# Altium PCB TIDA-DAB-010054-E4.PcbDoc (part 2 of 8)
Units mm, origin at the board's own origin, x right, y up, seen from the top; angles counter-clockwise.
Board outline 300 x 180 mm, 4 copper layers (Top Layer, Inner Layer1, Inner Layer2, Bottom Layer), stack 1.605 mm thick; 873 components, 388 nets, 2405 pads, 1542 vias.
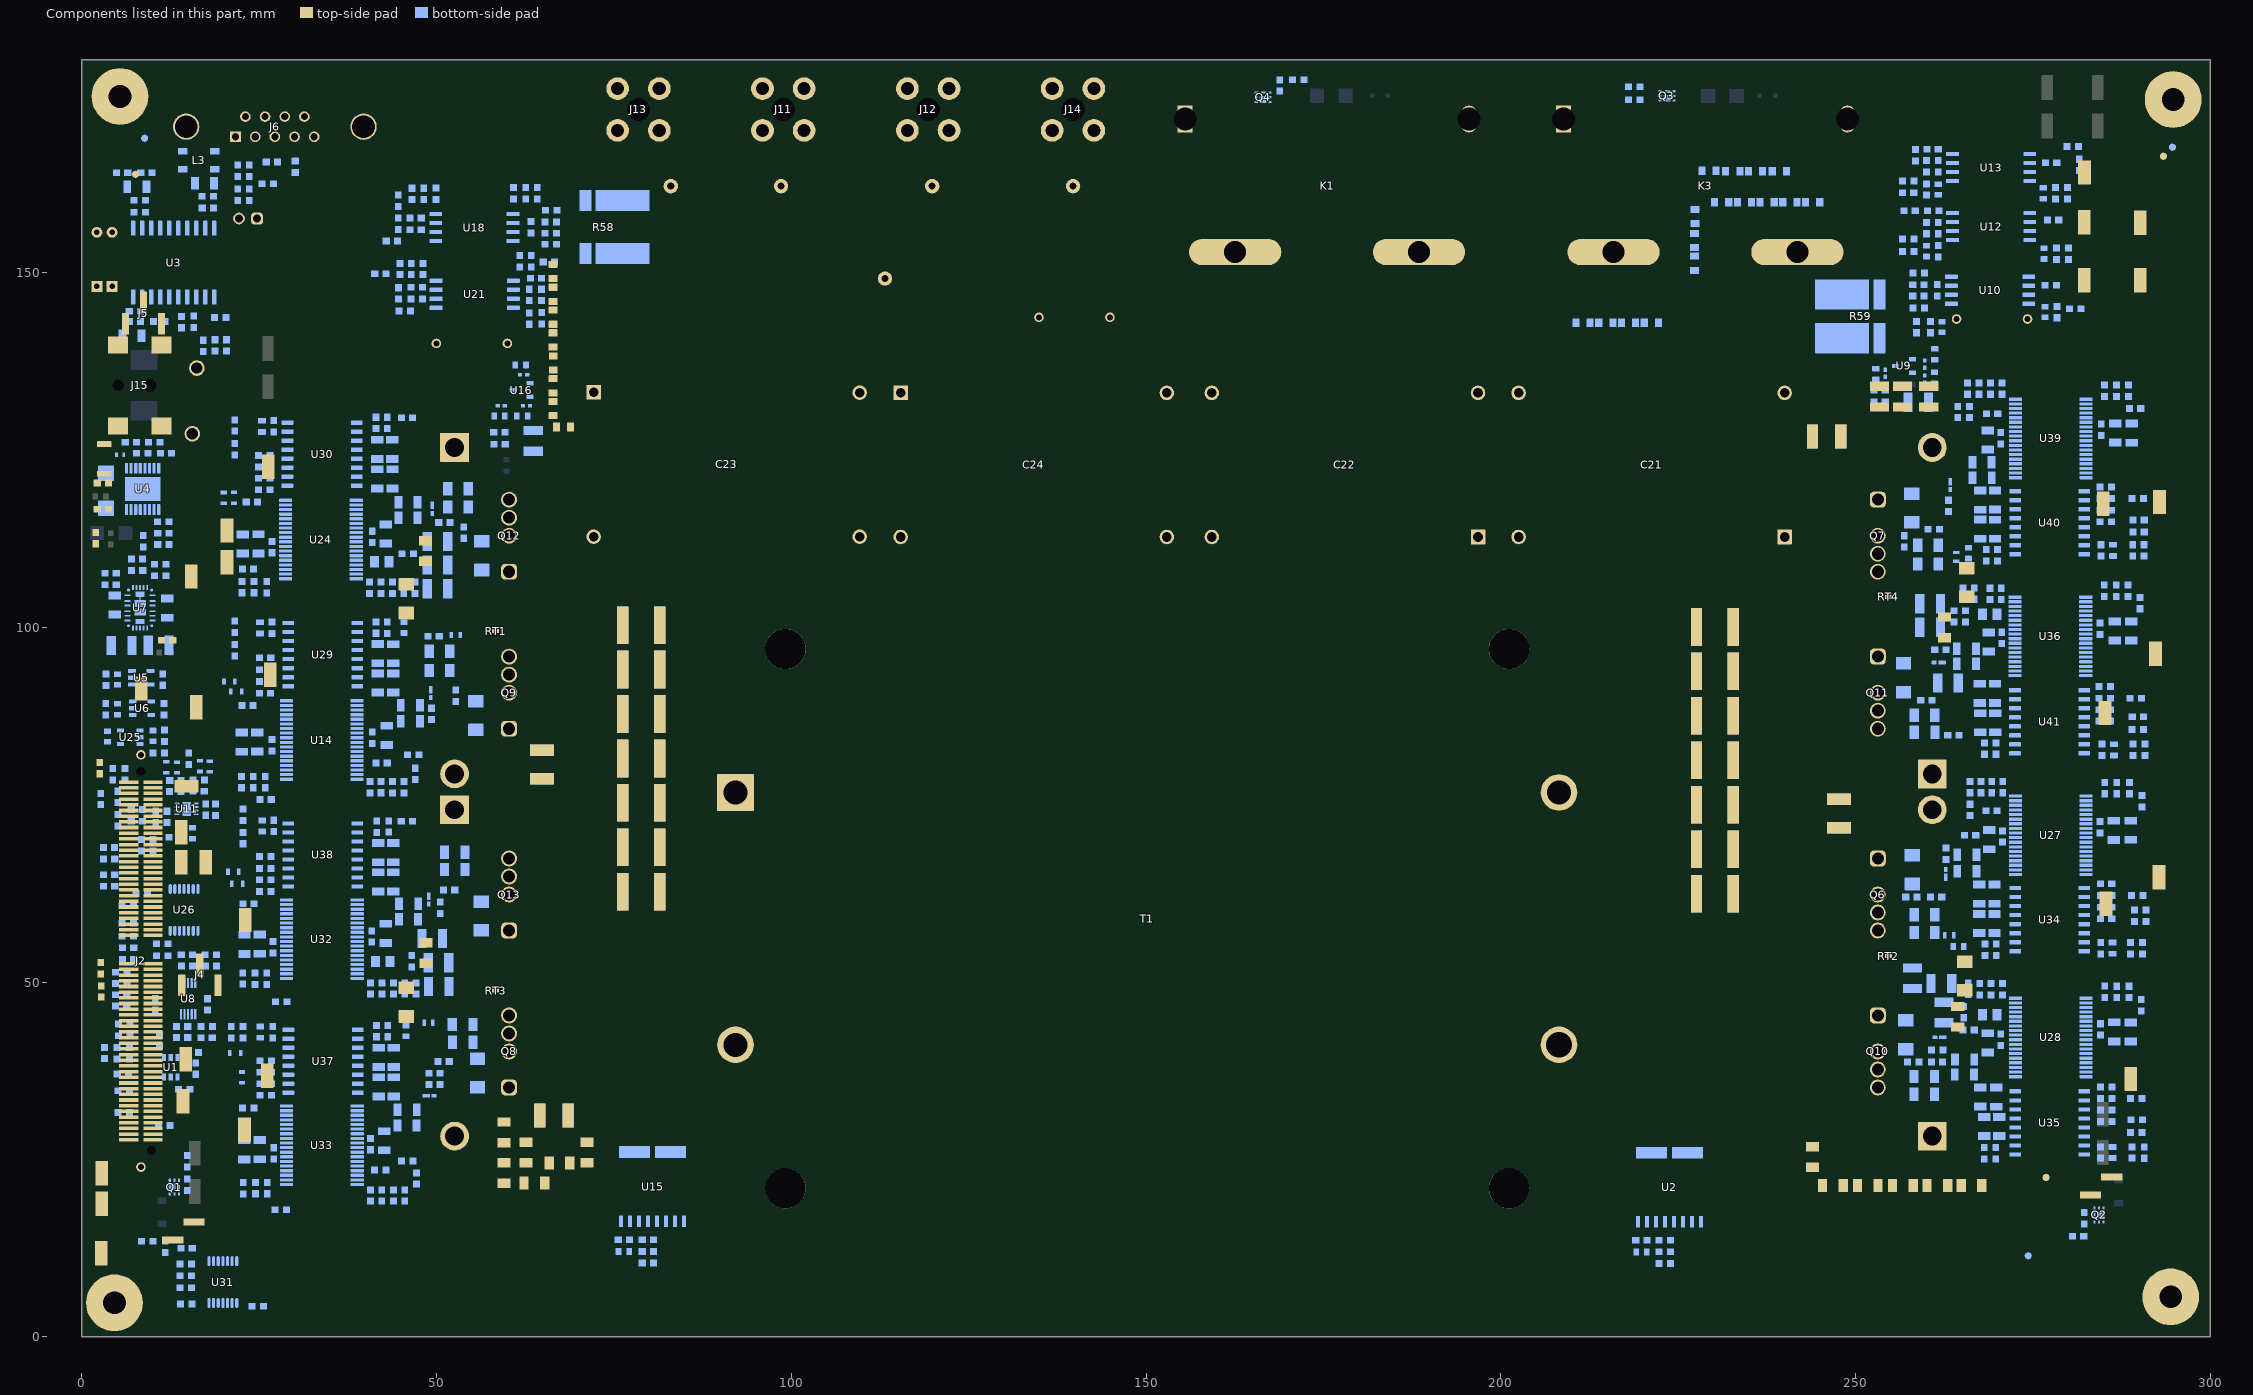
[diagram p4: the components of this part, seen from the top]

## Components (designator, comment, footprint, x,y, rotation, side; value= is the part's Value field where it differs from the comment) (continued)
FID4 "Fiducial" Fiducial10-20 8.89,168.91 r90 bottom
FID5 "Fiducial" Fiducial10-20 274.32,11.43 r90 bottom
FID6 "Fiducial" Fiducial10-20 294.64,167.64 r90 bottom
H1 "NY PMS 440 0025 PH" "NY PMS 440 0025 PH" 294.742,174.36 r0 top
H2 "NY PMS 440 0025 PH" "NY PMS 440 0025 PH" 5.419,174.805 r0 top
H3 "NY PMS 440 0025 PH" "NY PMS 440 0025 PH" 294.398,5.644 r0 top
H4 "NY PMS 440 0025 PH" "NY PMS 440 0025 PH" 4.644,4.8 r270 top locked
H5 "1902C" Keystone_1902C 294.742,174.36 r180 bottom
H6 "1902C" Keystone_1902C 5.419,174.805 r180 bottom
H7 "1902C" Keystone_1902C 294.398,5.644 r180 bottom
H8 "1902C" Keystone_1902C 4.653,4.8 r180 bottom locked
J1 "61000218321" Wurth_61000218321 14.35,14.91 r90 top
J2 "HSEC8-160-01-L-DV-A-BL" controlCARD-120HSEC 8.347,54.822 r270 top locked
J3 "61000218321" Wurth_61000218321 284.582,21.285 r90 top
J4 "61000318221" Wurth_61000318221 16.662,50.952 r90 top
J5 "61000318221" Wurth_61000318221 8.725,144.183 r90 top
J6 "618009231121" Wurth_618009231121 27.245,180.04 r90 top
J8 "999-11-113-10-000000" Mill-Max_999-11-113-10-000000 2.164,151.84 r90 top
J9 "999-11-113-10-000000" Mill-Max_999-11-113-10-000000 4.3,151.84 r90 top
J10 "61300211121" WURTH_61300211121 23.458,157.596 r180 top
J11 "74650073R" Wurth_WP-THRBU 98.893,172.96 r0 top
J12 "74650073R" Wurth_WP-THRBU 119.307,172.96 r90 top
J13 "74650073R" Wurth_WP-THRBU 78.48,172.96 r0 top
J14 "74650073R" Wurth_WP-THRBU 139.72,172.96 r0 top
J15 "PJ-002AH-SMT-TR" CUI_PJ-002AH-SMT 8.205,134.086 r0 top
K1 "G9KB-1A DC12" "FP-G9KB-1A DC12_PTH_RELAY_50MM0_36MM7-MFG" 175.52,159.27 r0 top
K3 "G9KB-1A DC12" "FP-G9KB-1A DC12_PTH_RELAY_50MM0_36MM7-MFG" 228.84,159.27 r0 top
L1 "74279228260" 0603 17.147,139.649 r270 bottom value="26 ohm"
L2 "74279228260" 0603 18.808,139.709 r270 bottom value="26 ohm"
L3 "ACT45B-101-2P-TL003" FP-ACT45B-101-2P-TL003_SMT_4MM5_3MM2-MFG 16.52,165.8 r0 bottom
L4 "74279228260" 0603 20.432,139.709 r270 bottom value="26 ohm"
L5 "74279228260" 0603 9.142,164.029 r180 bottom value="26 ohm"
L6 "74279228260" 0603 5.717,164.029 r0 bottom value="26 ohm"
L7 "74279228260" 0603 258.565,142.298 r270 bottom value="26 ohm"
L8 "74279228260" 0603 280.962,144.884 r0 bottom value="26 ohm"
L9 "74279228260" 0603 279.991,152.642 r270 bottom value="26 ohm"
L10 "74279228260" 0603 279.871,161.157 r270 bottom value="26 ohm"
L11 "74279228260" 0603 257.398,152.96 r180 bottom value="26 ohm"
L12 "74279228260" 0603 257.382,161.232 r180 bottom value="26 ohm"
L13 "74279228260" 0603 64.231,161.14 r90 bottom value="26 ohm"
L14 "74279228260" 0603 46.559,161.067 r90 bottom value="26 ohm"
L15 "74279228260" 0603 13.144,70.4 r0 bottom value="26 ohm"
L17 "74279228260" 0603 65.858,151.46 r0 bottom value="26 ohm"
L18 "74279228260" 0603 44.884,150.485 r90 bottom value="26 ohm"
LBL1 "THT-14-423-10" Label_650x200 104.8,6.14 r180 top
LOGO1 "DANGER HIGH VOLTAGE" IEC_HighVoltage_Medium 109.804,158.344 r0 top
LOGO2 "DANGER HIGH VOLTAGE" IEC_HighVoltage_Medium 97.968,151.155 r180 bottom
LOGO3 "CAUTION HOT SURFACE" IEC_HotSurface_Small 87.5,90.18 r180 bottom
LOGO4 "CAUTION HOT SURFACE" IEC_HotSurface_Small 79.865,35.14 r0 top
LOGO5 "CAUTION HOT SURFACE" IEC_HotSurface_Small 220.46,77.605 r0 top
LOGO6 "CAUTION HOT SURFACE" IEC_HotSurface_Small 81.6,38.74 r180 bottom
LOGO7 "CAUTION HOT SURFACE" IEC_HotSurface_Small 223.927,36.5 r0 top
LOGO8 "CAUTION HOT SURFACE" IEC_HotSurface_Small 126.74,155.46 r180 bottom
LOGO9 "CAUTION HOT SURFACE" IEC_HotSurface_Small 71.54,91.72 r0 top
LOGO10 "CAUTION HOT SURFACE" IEC_HotSurface_Small 77.953,141.63 r0 top
LOGO11 "CAUTION HOT SURFACE" IEC_HotSurface_Small 218.4,79 r180 bottom
LOGO12 "CAUTION HOT SURFACE" IEC_HotSurface_Small 222.631,37.719 r180 bottom
Logo13 "CE Mark" CE_Mark_5mm 182.68,4.8 r0 top
Logo14 "WEEE logo" WEEE_Minimum 202.566,5.841 r0 top
Logo15 "FCC disclaimer" FCC_disclaimer 154.98,1.62 r0 top
Logo16 "Pb-Free Symbol" Pb-Free_Overlay_Medium 211.9,4.794 r0 top
Logo17 "CAUTION.  READ USER GUIDE BEFORE USE" IEC_Caution_Medium 33.02,151.13 r0 top
Logo18 "ESD Susceptible" ESD_Overlay_Medium 193.9,5.188 r0 top
Logo19 "Texas Instruments" TI_Stacked_Overlay_Small 56.16,174.88 r0 top
MP1 "CD-02-05-247" FP-CD-02-05-247_THERM_PAD_24MM13_19MM05-MFG 354.178,12.628 r90 top
MP2 "CD-02-05-247" FP-CD-02-05-247_THERM_PAD_24MM13_19MM05-MFG 374.701,12.628 r90 top
MP3 "CR201-50VE" FP-CR201-50VE_PTH_HEATSINKS_34MM0_50MM0-MFG 262.049,51.28 r90 top locked
MP4 "CD-02-05-247" FP-CD-02-05-247_THERM_PAD_24MM13_19MM05-MFG 313.131,12.628 r90 top
MP5 "CD-02-05-247" FP-CD-02-05-247_THERM_PAD_24MM13_19MM05-MFG 333.654,12.628 r90 top
MP6 "CR201-50VE" FP-CR201-50VE_PTH_HEATSINKS_34MM0_50MM0-MFG 51.326,102.339 r270 top
MP7 "CR201-50VE" FP-CR201-50VE_PTH_HEATSINKS_34MM0_50MM0-MFG 262.049,102.339 r90 top locked
MP8 "CD-02-05-247" FP-CD-02-05-247_THERM_PAD_24MM13_19MM05-MFG 352.831,39.221 r90 top
MP9 "CD-02-05-247" FP-CD-02-05-247_THERM_PAD_24MM13_19MM05-MFG 373.355,39.221 r90 top
MP10 "CR201-50VE" FP-CR201-50VE_PTH_HEATSINKS_34MM0_50MM0-MFG 51.326,51.28 r270 top
MP11 "CD-02-05-247" FP-CD-02-05-247_THERM_PAD_24MM13_19MM05-MFG 311.785,39.221 r90 top
MP12 "CD-02-05-247" FP-CD-02-05-247_THERM_PAD_24MM13_19MM05-MFG 332.308,39.221 r90 top
MP13 "1474C" FP-1474C_HEX_STANDOFF_8-32_1IN2-MFG 99.176,96.936 r180 bottom
MP14 "1474C" FP-1474C_HEX_STANDOFF_8-32_1IN2-MFG 99.176,20.936 r180 bottom
MP15 "1474C" FP-1474C_HEX_STANDOFF_8-32_1IN2-MFG 201.176,96.936 r180 bottom
MP16 "1474C" FP-1474C_HEX_STANDOFF_8-32_1IN2-MFG 201.176,20.936 r180 bottom
MP17 "PMSSS 832 0063 PH" "FP-PMSSS 832 0063 PH_SCREW_0IN322-MFG" 201.176,20.936 r0 top
MP18 "PMSSS 832 0063 PH" "FP-PMSSS 832 0063 PH_SCREW_0IN322-MFG" 99.176,20.936 r0 top
MP19 "PMSSS 832 0063 PH" "FP-PMSSS 832 0063 PH_SCREW_0IN322-MFG" 201.176,96.936 r0 top
MP20 "PMSSS 832 0063 PH" "FP-PMSSS 832 0063 PH_SCREW_0IN322-MFG" 99.176,96.936 r0 top
NT1 "Net-Tie" Net-Tie7milsWide_20milsLong 8.251,104.071 r90 top net-tie
PWM1 "5015" Testpoint_Keystone_Miniature 26.618,93.304 r270 top
PWM2 "5015" Testpoint_Keystone_Miniature 26.294,122.597 r270 top
PWM3 "5015" Testpoint_Keystone_Miniature 26.188,36.822 r270 top
PWM4 "5015" Testpoint_Keystone_Miniature 23.089,58.742 r270 top
PWM5 "5015" Testpoint_Keystone_Miniature 285.285,61.035 r270 top
PWM6 "5015" Testpoint_Keystone_Miniature 288.755,36.341 r90 top
PWM7 "5015" Testpoint_Keystone_Miniature 284.867,117.404 r270 top
PWM8 "5015" Testpoint_Keystone_Miniature 285.144,87.907 r270 top
Q1 "CSD17318Q2" FP-CSD17318Q2_WSON6-MFG 13.083,21.096 r270 bottom
Q2 "CSD17318Q2" FP-CSD17318Q2_WSON6-MFG 284.295,17.179 r90 bottom
Q3 "CSD17318Q2" FP-CSD17318Q2_WSON6-MFG 223.414,174.88 r0 bottom
Q4 "CSD17318Q2" FP-CSD17318Q2_WSON6-MFG 166.51,174.686 r0 bottom
Q6 "C3M0030090K" TO-247-4 253.126,62.34 r270 top locked value=900V
Q7 "C3M0030090K" TO-247-4 253.126,112.899 r270 top locked value=900V
Q8 "C3M0075120K" TO-247-4 60.249,40.22 r90 top locked value=1200V
Q9 "C3M0075120K" TO-247-4 60.249,90.779 r90 top locked value=1200V
Q10 "C3M0030090K" TO-247-4 253.126,40.22 r270 top locked value=900V
Q11 "C3M0030090K" TO-247-4 253.126,90.779 r270 top locked value=900V
Q12 "C3M0075120K" TO-247-4 60.249,112.899 r90 top locked value=1200V
Q13 "C3M0075120K" TO-247-4 60.249,62.34 r90 top value=1200V
R1 "RT0603BRD07200RL" 0603 14.913,24.735 r270 bottom value=200
R2 "RT0603BRD0710KL" 0603 14.913,21.445 r90 bottom value=10.0k
R3 "RMCF0603ZT0R00" 0603 2.714,75.796 r270 bottom value=0
R4 "RT0603BRD07200RL" 0603 281.34,14.2 r0 bottom value=200
R5 "RT0603BRD0710KL" 0603 282.225,16.729 r270 bottom value=10.0k
R6 "CRM1206-JW-1R0ELF" 1206 48.467,110.747 r270 top value=1.0
R7 "CRM1206-JW-1R0ELF" 1206 264.386,45.12 r90 top value=1.0
R8 "ERJ-P06F6040V" 0805_HV 42.319,109.24 r0 bottom value=604
R9 "ERJ-P06F1001V" 0805_HV 268.893,45.372 r180 bottom value=1.00k
R10 "RMCF0603ZT0R00" 0603 2.718,51.959 r90 top value=0
R11 "ERJ-P06F1001V" 0805_HV 42.464,52.9 r0 bottom value=1.00k
R12 "ERJ-P06F6040V" 0805_HV 268.916,101.807 r180 bottom value=604
R13 "CRCW0603220RJNEA" 0603 253.366,131.773 r180 bottom value=220
R14 "CRCW0603220RJNEA" 0603 58.914,125.803 r180 bottom value=220
R15 "RMCF0603ZT0R00" 0603 5.15,72.807 r270 bottom value=0
R16 "CH0603-10RJFTA" FP-CH0603-10RJFTA_0603-MFG 52.729,98.901 r0 bottom value=10
R17 "CH0603-10RJFTA" FP-CH0603-10RJFTA_0603-MFG 263.195,56.591 r180 bottom value=10
R18 "CH0603-10RJFTA" FP-CH0603-10RJFTA_0603-MFG 48.895,44.272 r0 bottom value=10
R19 "RMCF0603ZT0R00" 0603 2.766,48.669 r90 top value=0
R20 "CRM1206-JW-1R0ELF" 1206 48.534,54.096 r270 top value=1.0
R21 "CRM1206-JW-1R0ELF" 1206 262.512,99.982 r90 top value=1.0
R22 "RMCF0603ZT0R00" 0603 260.842,167.356 r0 bottom value=0
R23 "RMCF0603ZT0R00" 0603 260.949,158.703 r0 bottom value=0
R24 "CRCW060310K0FKEA" 0603 51.136,114.747 r0 bottom value=10.0k
R25 "CRCW060310K0FKEA" 0603 49.301,87.786 r270 bottom value=10.0k
R26 "CRCW060310K0FKEA" 0603 262.716,68.097 r90 bottom value=10.0k
R27 "CRCW060310K0FKEA" 0603 261.504,40.415 r0 bottom value=10.0k
R28 "CRCW060310K0FKEA" 0603 5.106,76.085 r90 bottom value=10.0k
R29 "CH0603-10RJFTA" FP-CH0603-10RJFTA_0603-MFG 264.167,109.907 r90 bottom value=10
R30 "RC0603FR-0749R9L" 0603 17.621,42.161 r0 bottom value=49.9
R31 "CRCW060310K0FKEA" 0603 50.564,60.473 r270 bottom value=10.0k
R32 "CRCW060310K0FKEA" 0603 49.739,35.583 r180 bottom value=10.0k
R33 "RC0603FR-0749R9L" 0603 18.214,53.864 r0 bottom value=49.9
R34 "CRCW060310K0FKEA" 0603 261.945,96.842 r0 bottom value=10.0k
R35 "CRCW060310K0FKEA" 0603 263.078,117.097 r270 bottom value=10.0k
R36 "RMCF0603ZT0R00" 0603 63.104,143.494 r270 bottom value=0
R37 "RC0603JR-078K2L" 0603 223.088,10.338 r0 bottom value=8.2k
R38 "RMCF0603ZT0R00" 0603 14.085,143.011 r90 bottom value=0
R39 "RT0603BRD07200RL" 0603 171.44,177.14 r180 bottom value=200
R40 "RC0603JR-072K2L" 0603 223.114,11.989 r0 bottom value=2.2k
R41 "RMCF0603ZT0R00" 0603 15.826,143.04 r90 bottom value=0
R42 "RC0603FR-0749R9L" 0603 14.164,42.177 r180 bottom value=49.9
R43 "RT0603BRD0710KL" 0603 168.86,176.34 r90 bottom value=10.0k
R45 "RC0603JR-078K2L" 0603 79.807,10.414 r0 bottom value=8.2k
R46 "RC0603JR-071K2L" 0603 79.807,12.04 r0 bottom value=1.2k
R48 "RT0603BRD07200RL" 0603 218.8,176.16 r0 bottom value=200
R51 "RT0603BRD0710KL" 0603 218.8,174.32 r0 bottom value=10.0k
R52 "CRCW060310K0FKEA" 0603 10.952,143.086 r180 bottom value=10.0k
R53 "CR0603-10W-000T" FP-CR0603-10W-000T_0603-MFG 30.112,164.877 r90 bottom value=0uΩ
R54 "CRCW060356R2FKEA" 0603 22.017,160.95 r270 bottom value=56.2
R55 "CRCW060356R2FKEA" 0603 22.008,164.327 r270 bottom value=56.2
R56 "CR0603-10W-000T" FP-CR0603-10W-000T_0603-MFG 26.83,165.547 r0 bottom value=0uΩ
R58 "WSL36373L000FEA" WSL3637_0_002 75.106,156.382 r270 bottom value=0.003
R59 "WSL36371L500FEA" FP-WSL36371L500FEA_3637-MFG 249.251,143.818 r90 bottom value=1.5m
R61 "RMCF0603ZT0R00" 0603 47.246,147.897 r180 bottom value=0
R63 "RMCF0603ZT0R00" 0603 47.224,146.255 r180 bottom value=0
R64 "RT0805BRD07634KL" 0805_HV1 239.251,164.256 r0 bottom value=634k
R66 "CRCW12061M00FKEA" 1206 59.525,28.82 r90 top value=1.00Meg
R68 "RC0603JR-070RL" 0603 3.016,120.316 r0 top value=0
R69 "RC0603FR-07330KL" 0603 6.957,126.082 r180 bottom value=330k
R70 "RC0603FR-072K1L" 0603 3.016,116.631 r180 top value=2.10k
R71 "RC0603JR-0720KL" 0603 8.557,124.507 r180 bottom value=20k
R72 "CRCW0603100KJNEA" 0603 2.564,80.159 r270 top value=100k
R73 "CRCW06035K36FKEA" 0603 11.533,113.24 r0 bottom value=5.36k
R74 "RC0603FR-0719K1L" 0603 11.531,114.872 r180 bottom value=19.1k
R75 "RC0603FR-0730KL" 0603 10.23,126.082 r180 bottom value=30.0k
R76 "RC0603FR-072K1L" 0603 2,112.57 r90 top value=2.10k
R77 "RC0603JR-070RL" 0603 11.905,124.507 r180 bottom value=0
R78 "RC0603JR-070RL" 0603 8.713,112.122 r90 bottom value=0
R79 "CRCW060310K0FKEA" 0603 5.569,46.633 r0 bottom value=10.0k
R80 "PAT0603E4002BST1" 0603 7.822,107.986 r180 bottom value=40.0k
R81 "CRCW0603499RFKEAC" 0603 12.058,98.161 r0 top value=499
R82 "CRCW060310K0FKEA" 0603 5.569,48.223 r0 bottom value=10.0k
R83 "RG1608P-103-B-T5" 0603 11.074,108.877 r0 bottom value=10.0k
R84 "RC0603FR-0713KL" 0603 11.076,107.275 r180 bottom value=13.0k
R85 "RMCF0603ZT0R00" 0603S 21.8,90.935 r0 bottom value=0
R86 "RC0603FR-0749R9L" 0603 14.857,53.864 r180 bottom value=49.9
R87 "CRCW0603100KJNEAC" 0603 253.366,133.396 r0 bottom value=100k
R88 "RC1210JR-07160RL" 1210 258.811,131.7 r0 bottom value=160
R89 "TNPW060310R0BEEA" 0603 258.845,146.672 r0 bottom value=10.0
R90 "RC0603JR-073K6L" 0603 24.206,78.181 r90 bottom value=3.6k
R91 "TNPW060310R0BEEA" 0603 258.845,148.272 r0 bottom value=10.0
R92 "RC0603FR-0740R2L" 0603 277.5,148.181 r0 bottom value=40.2
R93 "RC0603JR-073K6L" 0603 22.6,105.662 r90 bottom value=3.6k
R94 "RC0603JR-073K6L" 0603 288.583,77.332 r270 bottom value=3.6k
R95 "RT0805BRD07634KL" 0805_HV1 235.893,164.256 r180 bottom value=634k
R96 "RT0805BRD07634KL" 0805_HV1 227.3,151.298 r270 bottom value=634k
R97 "RT0805BRD07634KL" 0805_HV1 232.687,164.256 r180 bottom value=634k
R98 "RT0805BRD07634KL" 0805_HV1 227.3,154.504 r90 bottom value=634k
R99 "RC0603JR-073K6L" 0603 288.51,48.616 r270 bottom value=3.6k
R100 "RT0805BRD07634KL" 0805_HV1 229.33,164.336 r0 bottom value=634k
R101 "RT0805BRD07634KL" 0805_HV1 211.594,142.912 r180 bottom value=634k
R102 "RT0805BRD07634KL" 0805_HV1 227.34,157.891 r90 bottom value=634k
R103 "RT0805BRD07634KL" 0805_HV1 214.799,142.912 r180 bottom value=634k
R104 "RC0603JR-073K6L" 0603 24.46,50.482 r90 bottom value=3.6k
R105 "RT0805BRD07634KL" 0805_HV1 231.119,159.888 r180 bottom value=634k
R106 "RT0805BRD07634KL" 0805_HV1 234.324,159.888 r180 bottom value=634k
R107 "RT0805BRD07634KL" 0805_HV1 218.004,142.912 r0 bottom value=634k
R108 "RT0805BRD07634KL" 0805_HV1 237.529,159.888 r180 bottom value=634k
R109 "RT0805BRD07634KL" 0805_HV1 221.209,142.912 r180 bottom value=634k
R110 "RT0805BRD07634KL" 0805_HV1 240.734,159.888 r0 bottom value=634k
R111 "RT0805BRD07634KL" 0805_HV1 243.939,159.888 r180 bottom value=634k
R112 "RT0805BRD07634KL" 0805_HV1 67.915,128.237 r180 top value=634k
R114 "RT0603BRD073K32L" 0603 259.976,156.252 r270 bottom value=3.32k
R115 "RT0603BRD077K68L" 0603 259.976,164.956 r270 bottom value=7.68k
R116 "RC0603FR-0740R2L" 0603 277.82,157.4 r0 bottom value=40.2
R117 "RC0603FR-0740R2L" 0603 277.54,165.44 r0 bottom value=40.2
R118 "RC0603FR-07100RL" 0603 281.525,165.15 r270 bottom value=100
R123 "CRCW06030000Z0EA" 0603 5.829,37.059 r180 bottom value=10.0k
R124 "RT0805BRD07634KL" 0805_HV1 66.455,130.817 r270 top value=634k
R125 "CRCW060351R0JNEA" 0603 6.756,39.98 r90 bottom value=51
R126 "RC0603FR-0768RL" 0603 3.875,67.35 r0 bottom value=68.0
R127 "CRCW12061M00FKEA" 1206 243.9,25.346 r90 top value=1.00Meg
R128 "CRCW12061M00FKEA" 1206 62.64,25.98 r90 top value=1.00Meg
R129 "RC1210JR-07160RL" 1210 63.647,126.267 r90 bottom value=160
R130 "RC0603JR-073K6L" 0603 24.511,20.968 r90 bottom value=3.6k
R131 "CRCW0603100KJNEAC" 0603 58.891,127.467 r0 bottom value=100k
R133 "RC0603JR-073K6L" 0603 288.363,105.157 r270 bottom value=3.6k
R134 "RC0603JR-073K6L" 0603 288.444,133.309 r270 bottom value=3.6k
R135 "RT0603DRE079K2L" 0603 10.457,73.275 r270 bottom value=8.06k
R136 "TNPW060310R0BEEA" 0603 66.136,157.107 r180 bottom value=10.0
R137 "RMCF0603ZT0R00" 0603 47.077,157.671 r180 bottom value=0
R138 "TNPW060310K0BEEA" TNPW0603 11.944,80.269 r90 bottom value=10.0k
R139 "CRCW060368R1FKEA" 0603 7.801,72.66 r180 bottom value=68.1
R140 "TNPW060310R0BEEA" 0603 66.136,155.52 r180 bottom value=10.0
R141 "RMCF0603ZT0R00" 0603 47.077,156.019 r180 bottom value=0
R142 "TNPW060310K0BEEA" TNPW0603 13.455,80.252 r90 bottom value=10.0k
R143 "RT0603DRE079K2L" 0603 13.227,78.395 r180 bottom value=8.06k
R144 "RMCF0603ZT0R00" 0603S 21.48,118.26 r90 bottom value=0
R145 "RT0805BRD07634KL" 0805_HV1 66.458,134.03 r270 top value=634k
R146 "RT0805BRD07634KL" 0805_HV1 66.476,137.247 r270 top value=634k
R147 "RMCF0603ZT0R00" 0603S 20.839,92.351 r0 bottom value=0
R148 "RT0805BRD07634KL" 0805_HV1 66.441,140.497 r90 top value=634k
R149 "RT0805BRD07634KL" 0805_HV1 66.442,143.698 r270 top value=634k
R150 "RMCF0603ZT0R00" 0603S 20.051,118.22 r90 bottom value=0
R151 "RT0805BRD07634KL" 0805_HV1 66.455,146.917 r270 top value=634k
R152 "RT0805BRD07634KL" 0805_HV1 66.455,150.137 r270 top value=634k
R153 "RT0603DRE079K2L" 0603 18.886,74.297 r270 bottom value=8.06k
R154 "RC0603FR-0715KL" 0603 53.858,113.335 r270 bottom value=15.0k
R155 "ERJ3EKF1802V" 0603 45.861,129.512 r0 bottom value=18.0k
R156 "TNPW060310K0BEEA" TNPW0603 18.088,80.39 r90 bottom value=10.0k
R157 "CRCW060368R1FKEA" 0603 9.26,70.077 r180 bottom value=68.1
R158 "RT0603BRD0710KL" 0603 64.818,146.827 r90 bottom value=10.0k
R159 "TNPW060310K0BEEA" TNPW0603 16.69,80.42 r90 bottom value=10.0k
R160 "RT0603DRE079K2L" 0603 16.49,76.89 r0 bottom value=8.06k
R163 "RG1608P-103-B-T5" 0603 10.884,82.264 r0 bottom value=10.0k
R164 "CRCW06030000Z0EA" 0603 5.004,39.98 r270 bottom value=10.0k
R166 "CRCW060368R1FKEA" 0603 6.107,79.279 r270 bottom value=68.1
R167 "CRCW060351R0JNEA" 0603 3.226,40.005 r90 bottom value=51
R168 "CRCW060368R1FKEA" 0603 3.88,63.492 r0 bottom value=68.1
R169 "RG1608P-103-B-T5" 0603 11.682,84.713 r90 bottom value=10.0k
R171 "RC0603FR-072KL" 0603 43.082,128.797 r90 bottom value=2.00k
R172 "ERJ-3GEY0R00V" 0603 11.382,53.695 r180 bottom value=0
R173 "ERJ-3GEY0R00V" 0603 6.563,53.22 r0 bottom value=0
R174 "CRCW060310K0FKEA" 0603 23.531,61.028 r180 bottom value=10.0k
R175 "CRCW060310K0FKEA" 0603 23.488,32.266 r180 bottom value=10.0k
R176 "CRCW060310K0FKEA" 0603 24.011,117.639 r180 bottom value=10.0k
R177 "CRCW060310K0FKEA" 0603 23.385,88.981 r180 bottom value=10.0k
R178 "CRCW060310K0FKEA" 0603 6.563,54.848 r0 bottom value=10.0k
R179 "CRCW060310K0FKEA" 0603 6.516,56.453 r180 bottom value=10.0k
R180 "CRCW060310K0FKEA" 0603 6.504,58.277 r180 bottom value=10.0k
R181 "CRCW060310K0FKEA" 0603 6.526,60.762 r180 bottom value=10.0k
R182 "CRCW060310K0FKEA" 0603 8.486,62.495 r180 bottom value=10.0k
R183 "RCA06031K00JNEA" 0603 42.282,80.865 r0 bottom value=1.0k
R185 "CRCW0603100KJNEA" 0603 25.933,75.717 r0 bottom value=100k
R186 "CRCW060310K0FKEA" 0603 22.53,78.181 r90 bottom value=10.0k
R187 "CRCW0603100KJNEA" 0603 26.086,105.654 r90 bottom value=100k
R188 "RT0603BRD07107KL" 0603 46.745,82.029 r0 bottom value=107k
R189 "RG1608P-303-B-T5" 0603 47.039,79.331 r90 bottom value=30.0k
R190 "CRCW060310K0FKEA" 0603 23.457,108.204 r180 bottom value=10.0k
R191 "RT0603BRD07107KL" 0603 45.982,110.357 r180 bottom value=107k
R192 "RG1608P-303-B-T5" 0603 46.997,105.574 r90 bottom value=30.0k
R193 "RMCF0603ZT0R00" 0603 290.1,60.14 r180 bottom value=0
R194 "RMCF0603ZT0R00" 0603 289.595,30.608 r180 bottom value=0
R196 "RT0603BRD0716K2L" 0603 42.213,77.472 r90 bottom value=16.2k
R197 "RT0603BRD0749K9L" 0603 45.429,77.465 r90 bottom value=49.9k
R198 "RT0603BRD0716K2L" 0603 42.192,105.574 r90 bottom value=16.2k
R199 "RT0603BRD0749K9L" 0603 45.4,105.574 r90 bottom value=49.9k
R200 "CRCW0603100RJNEA" 0603 25.856,92.351 r0 bottom value=100
R201 "CRCW0603100RJNEA" 0603 25.744,120.989 r0 bottom value=100
R202 "CRCW0603100RJNEA" 0603 25.856,94.029 r0 bottom value=100
R203 "CRCW0603100RJNEA" 0603 25.744,122.597 r0 bottom value=100
R204 "CRCW060310K0FKEA" 0603 5.593,49.799 r0 bottom value=10.0k
R205 "CRCW060310K0FKEA" 0603 5.595,51.39 r0 bottom value=10.0k
R206 "RMCF0603ZT0R00" 0603 290.1,58.533 r180 bottom value=0
R207 "RMCF0603ZT0R00" 0603 289.56,28.788 r180 bottom value=0
R208 "RC0603FR-0715KL" 0603 52.729,90.35 r270 bottom value=15.0k
R209 "CRCW12062R00JNEA" 1206 50.433,93.883 r0 bottom value=2.0
R210 "RMCF0603ZT0R00" 0603S 22.611,36.563 r90 bottom value=0
R211 "RMCF0603ZT0R00" 0603S 21.931,63.853 r0 bottom value=0
R212 "RMCF0603ZT0R00" 0603S 21.665,40 r0 bottom value=0
R213 "RMCF0603ZT0R00" 0603S 21.395,65.532 r0 bottom value=0
R214 "CRCW0603100RJNEA" 0603 21.6,125.099 r90 bottom value=100
R215 "CRCW12062R00JNEA" 1206 53.04,116.923 r0 bottom value=2.0
R216 "CRCW12062R00JNEA" 1206 50.433,96.611 r0 bottom value=2.0
R217 "ERJ3EKF1802V" 0603 49.613,98.725 r0 bottom value=18.0k
R218 "CRCW12062R00JNEA" 1206 53.04,119.52 r0 bottom value=2.0
R219 "CRCW12100000Z0EA" 1210 50.167,105.422 r0 bottom value=0
R220 "CRCW0603100RJNEA" 0603 21.605,96.767 r90 bottom value=100
R221 "CRCW12100000Z0EA" 1210 50.335,49.377 r180 bottom value=0
R222 "CRCW12061M00FKEA" 1206 246.794,21.345 r180 top value=1.00Meg
R223 "RC0603FR-072KL" 0603 43.084,99.945 r90 bottom value=2.00k
R224 "CRCW12100000Z0EA" 1210 50.167,108.759 r0 bottom value=0
R225 "CRCW12100000Z0EA" 1210 50.297,52.726 r180 bottom value=0
R226 "CRCW12061M00FKEA" 1206 59.525,23.085 r90 top value=1.00Meg
R227 "CRCW12100000Z0EA" 1210 50.167,112.097 r0 bottom value=0
R228 "CRCW12061M00FKEA" 1206 251.713,21.345 r180 top value=1.00Meg
R229 "CRCW12100000Z0EA" 1210 49.418,56.137 r180 bottom value=0
R230 "ERJ-3GEY0R00V" 0603 14.675,6.939 r0 bottom value=0
R231 "ERJ-3GEY0R00V" 0603 9.253,13.495 r0 bottom value=0
R232 "CRCW060310K0FKEA" 0603 289.489,89.999 r180 bottom value=10.0k
R233 "CRCW060310K0FKEA" 0603 289.761,118.129 r180 bottom value=10.0k
R234 "CRCW060310K0FKEA" 0603 289.56,33.58 r180 bottom value=10.0k
R235 "CRCW060310K0FKEA" 0603 289.685,62.196 r180 bottom value=10.0k
R236 "CRCW060310K0FKEA" 0603 14.675,8.604 r0 bottom value=10.0k
R237 "CRCW060310K0FKEA" 0603 24.848,4.319 r180 bottom value=10.0k
R238 "CRCW060310K0FKEA" 0603 14.803,12.482 r0 bottom value=10.0k
R239 "CRCW060310K0FKEA" 0603 14.675,10.27 r0 bottom value=10.0k
R240 "CRCW060310K0FKEA" 0603 11.787,12.695 r90 bottom value=10.0k
R241 "RCA06031K00JNEA" 0603 269.144,74.145 r180 bottom value=1.0k
R243 "CRCW0603100KJNEA" 0603 285.099,77.332 r270 bottom value=100k
R244 "CRCW060310K0FKEA" 0603 290.347,75.489 r270 bottom value=10.0k
R245 "CRCW0603100KJNEA" 0603 285.105,48.633 r270 bottom value=100k
R246 "RT0603BRD07107KL" 0603 266.128,70.695 r0 bottom value=107k
R247 "RG1608P-303-B-T5" 0603 266.119,74.255 r270 bottom value=30.0k
R248 "CRCW060310K0FKEA" 0603 290.246,46.736 r270 bottom value=10.0k
R249 "RT0603BRD07107KL" 0603 265.911,43.261 r180 bottom value=107k
R250 "RG1608P-303-B-T5" 0603 265.241,45.77 r270 bottom value=30.0k
R251 "RMCF0603ZT0R00" 0603 289.871,115.112 r180 bottom value=0
R252 "RMCF0603ZT0R00" 0603 289.775,87.404 r180 bottom value=0
R255 "RT0603BRD0716K2L" 0603 269.181,77.482 r270 bottom value=16.2k
R256 "RT0603BRD0749K9L" 0603 266.119,77.482 r270 bottom value=49.9k
R257 "RT0603BRD0716K2L" 0603 269.088,49.007 r270 bottom value=16.2k
R258 "RT0603BRD0749K9L" 0603 265.88,49.047 r270 bottom value=49.9k
R259 "CRCW0603100RJNEA" 0603 285.285,62.204 r180 bottom value=100
R260 "CRCW0603100RJNEA" 0603 285.325,33.58 r180 bottom value=100
R261 "CRCW0603100RJNEA" 0603 285.285,60.56 r180 bottom value=100
R262 "CRCW0603100RJNEA" 0603 285.325,31.979 r180 bottom value=100
R263 "RMCF0603ZT0R00" 0603 289.871,113.432 r180 bottom value=0
R264 "RMCF0603ZT0R00" 0603 289.761,85.576 r180 bottom value=0
R267 "RC0603FR-0715KL" 0603 261.34,61.975 r0 bottom value=15.0k
R272 "CRCW12062R00JNEA" 1206 259.699,59.486 r180 bottom value=2.0
R273 "RC0603FR-0715KL" 0603 261.468,38.748 r0 bottom value=15.0k
R274 "CRCW12062R00JNEA" 1206 259.655,36.68 r180 bottom value=2.0
R275 "CRCW12062R00JNEA" 1206 259.699,56.98 r180 bottom value=2.0
R276 "ERJ3EKF1802V" 0603 257.863,61.975 r0 bottom value=18.0k
R277 "CRCW12062R00JNEA" 1206 259.655,34.191 r180 bottom value=2.0
R278 "ERJ3EKF1802V" 0603 258.113,38.748 r0 bottom value=18.0k
R279 "CRCW0603100RJNEA" 0603 290.41,54.774 r90 bottom value=100
R280 "CRCW0603100RJNEA" 0603 290.652,25.971 r90 bottom value=100
R281 "CRCW12061M00FKEA" 1206 63.815,21.697 r180 top value=1.00Meg
R282 "RC0603FR-072KL" 0603 268.23,54.543 r270 bottom value=2.00k
R284 "RC0603FR-072KL" 0603 268.113,25.896 r270 bottom value=2.00k
R285 "CRCW12061M00FKEA" 1206 256.655,21.345 r180 top value=1.00Meg
R286 "CRCW0603100KJNEA" 0603 28.131,47.219 r180 bottom value=100k
R287 "CRCW060310K0FKEA" 0603 22.712,50.5 r90 bottom value=10.0k
R288 "RCA06031K00JNEA" 0603 42.107,23.533 r0 bottom value=1.0k
R289 "RT0603BRD07107KL" 0603 46.525,52.926 r90 bottom value=107k
R290 "RG1608P-303-B-T5" 0603 47.134,49.097 r90 bottom value=30.0k
R291 "CRCW0603100KJNEA" 0603 28.08,17.932 r180 bottom value=100k
R292 "CRCW060310K0FKEA" 0603 22.784,20.955 r90 bottom value=10.0k
R293 "RT0603BRD07107KL" 0603 45.882,24.78 r0 bottom value=107k
R294 "RG1608P-303-B-T5" 0603 47.217,22.322 r90 bottom value=30.0k
R298 "RT0603BRD0716K2L" 0603 42.343,49.097 r90 bottom value=16.2k
R299 "RT0603BRD0749K9L" 0603 45.561,49.097 r90 bottom value=49.9k
R301 "RT0603BRD0716K2L" 0603 42.303,19.923 r90 bottom value=16.2k
R302 "RT0603BRD0749K9L" 0603 45.55,19.923 r90 bottom value=49.9k
R303 "CRCW0603100RJNEA" 0603 25.945,35.679 r0 bottom value=100
R304 "CRCW0603100RJNEA" 0603 25.897,64.406 r0 bottom value=100
R305 "CRCW0603100RJNEA" 0603 25.945,37.297 r0 bottom value=100
R306 "CRCW0603100RJNEA" 0603 25.897,66.006 r0 bottom value=100
R311 "RC0603FR-0715KL" 0603 49.739,37.155 r180 bottom value=15.0k
R316 "CRCW12062R00JNEA" 1206 53.714,41.515 r0 bottom value=2.0
R317 "RC0603FR-0715KL" 0603 51.791,62.972 r180 bottom value=15.0k
R318 "CRCW12062R00JNEA" 1206 52.584,65.84 r0 bottom value=2.0
R319 "CRCW12062R00JNEA" 1206 53.695,44.031 r0 bottom value=2.0
R320 "ERJ3EKF1802V" 0603 51.016,38.803 r0 bottom value=18.0k
R321 "CRCW12062R00JNEA" 1206 52.584,68.295 r0 bottom value=2.0
R322 "ERJ3EKF1802V" 0603 45.852,72.648 r0 bottom value=18.0k
R323 "CRCW0603100RJNEA" 0603 21.114,42.947 r270 bottom value=100
R324 "CRCW0603100RJNEA" 0603 22.759,70.294 r90 bottom value=100
R325 "RC0603FR-072KL" 0603 43.165,43.097 r90 bottom value=2.00k
R326 "RC0603FR-072KL" 0603 43.304,71.923 r90 bottom value=2.00k
R327 "CRCW12061M00FKEA" 1206 67.36,24.48 r180 top value=1.00Meg
R328 "RCA06031K00JNEA" 0603 269.222,130.072 r180 bottom value=1.0k
R329 "CRCW0603100KJNEA" 0603 285.07,133.309 r270 bottom value=100k
R330 "CRCW060310K0FKEA" 0603 289.38,130.835 r0 bottom value=10.0k
R331 "RT0603BRD07107KL" 0603 264.405,130.333 r270 bottom value=107k
R332 "RG1608P-303-B-T5" 0603 266.047,130.333 r270 bottom value=30.0k
R335 "RT0603BRD0716K2L" 0603 268.998,133.634 r270 bottom value=16.2k
R336 "RT0603BRD0749K9L" 0603 265.755,133.631 r270 bottom value=49.9k
R338 "CRCW12100000Z0EA" 1210 260.5,100.004 r180 bottom value=0
R339 "CRCW12100000Z0EA" 1210 256.592,132.495 r90 top value=0
R340 "CRCW12100000Z0EA" 1210 262.46,45.716 r270 bottom value=0
R341 "CRCW12100000Z0EA" 1210 260.5,103.304 r180 bottom value=0
R342 "CRCW12100000Z0EA" 1210 253.372,132.495 r90 top value=0
R343 "CRCW12100000Z0EA" 1210 258.005,50.549 r270 bottom value=0
R344 "CRCW0603100KJNEA" 0603 285.033,105.157 r270 bottom value=100k
R345 "CRCW060310K0FKEA" 0603 290.068,103.403 r270 bottom value=10.0k
R346 "RT0603BRD07107KL" 0603 264.667,100.755 r180 bottom value=107k
R347 "RG1608P-303-B-T5" 0603 264.667,102.34 r0 bottom value=30.0k
R350 "RT0603BRD0716K2L" 0603 268.947,104.698 r270 bottom value=16.2k
R351 "RT0603BRD0749K9L" 0603 265.13,104.75 r270 bottom value=49.9k
R352 "CRCW0603100RJNEA" 0603 285.236,118.129 r180 bottom value=100
R353 "CRCW0603100RJNEA" 0603 285.089,89.999 r180 bottom value=100
R354 "CRCW0603100RJNEA" 0603 285.216,116.469 r180 bottom value=100
R355 "CRCW0603100RJNEA" 0603 285.089,88.382 r180 bottom value=100
R359 "CRCW12061M00FKEA" 1206 261.518,21.345 r180 top value=1.00Meg
R361 "CRCW12061M00FKEA" 1206 71.25,25.98 r270 top value=1.00Meg
R362 "RC0603FR-0715KL" 0603 261,113.811 r0 bottom value=15.0k
R363 "CRCW12061M00FKEA" 1206 266.327,21.345 r180 top value=1.00Meg
R368 "CRCW12062R00JNEA" 1206 260.203,111.547 r180 bottom value=2.0
R369 "RC0603FR-0715KL" 0603 259.981,89.708 r0 bottom value=15.0k
R370 "CRCW12062R00JNEA" 1206 259.697,87.601 r180 bottom value=2.0
R371 "CRCW12062R00JNEA" 1206 260.2,108.92 r180 bottom value=2.0
R372 "ERJ3EKF1802V" 0603 256.862,112.099 r90 bottom value=18.0k
R373 "CRCW12062R00JNEA" 1206 259.715,85.202 r180 bottom value=2.0
R374 "ERJ3EKF1802V" 0603 263.786,84.766 r180 bottom value=18.0k
R375 "CRCW0603100RJNEA" 0603 290.625,110.828 r90 bottom value=100
R376 "CRCW0603100RJNEA" 0603 290.786,82.735 r90 bottom value=100
R377 "RC0603FR-072KL" 0603 268.405,110.133 r270 bottom value=2.00k
R378 "RC0603FR-072KL" 0603 268.164,82.904 r270 bottom value=2.00k
R379 "CRCW12100000Z0EA" 1210 263.009,92.125 r180 bottom value=0
R380 "CRCW12100000Z0EA" 1210 260.298,132.495 r90 top value=0
R381 "CRCW12100000Z0EA" 1210 262.08,49.8 r0 bottom value=0
RT1 "TMP6131DECR" DEC0002A 58.35,99.457 r180 top
RT2 "TMP6131DECR" DEC0002A 254.63,53.668 r0 top
RT3 "TMP6131DECR" DEC0002A 58.35,48.797 r180 top
RT4 "TMP6131DECR" DEC0002A 254.63,104.283 r0 top
S1 "SKRKAEE020" SW_SKRKAE 3.199,123.715 r270 top
T1 "61259" FP-61259_PTH_XFRMR_130MM0_90MM0-MFG 150.176,58.936 r0 top locked
TP1 "5003" Keystone5003 113.22,149.14 r90 top
TP2 "5003" Keystone5003 119.86,162.16 r90 top
TP3 "5003" Keystone5003 98.57,162.16 r0 top
TP4 "5003" Keystone5003 83.04,162.16 r90 top
TP5 "5003" Keystone5003 139.72,162.16 r90 top
TP6 "5015" Testpoint_Keystone_Miniature 15.459,107.156 r90 top
TP7 "5010" Keystone5010 16.256,136.525 r180 top
TP8 "5015" Testpoint_Keystone_Miniature 14.78,77.615 r0 top
TP9 "5015" Testpoint_Keystone_Miniature 14.044,71.125 r90 top
TP10 "5015" Testpoint_Keystone_Miniature 8.408,91.367 r90 top
TP11 "5011" Keystone5011 15.621,127.254 r0 top
TP12 "5015" Testpoint_Keystone_Miniature 14.3,33.223 r90 top
TP13 "5015" Testpoint_Keystone_Miniature 282.225,148.903 r90 top
TP14 "5015" Testpoint_Keystone_Miniature 282.225,157.076 r90 top
TP15 "5015" Testpoint_Keystone_Miniature 282.25,164.081 r270 top
TP16 "5015" Testpoint_Keystone_Miniature 2.851,18.777 r270 top
TP17 "5015" Testpoint_Keystone_Miniature 17.52,66.89 r90 top
TP18 "5015" Testpoint_Keystone_Miniature 2.781,11.802 r270 top
TP19 "5015" Testpoint_Keystone_Miniature 14.057,66.89 r90 top
TP20 "5015" Testpoint_Keystone_Miniature 14.681,39.141 r90 top
TP21 "5015" Testpoint_Keystone_Miniature 20.495,113.643 r90 top
TP22 "5015" Testpoint_Keystone_Miniature 20.495,109.15 r90 top
TP23 "5015" Testpoint_Keystone_Miniature 292.823,117.654 r90 top
TP24 "5015" Testpoint_Keystone_Miniature 290.09,148.903 r90 top
TP25 "5015" Testpoint_Keystone_Miniature 22.96,29.2 r90 top
TP26 "5015" Testpoint_Keystone_Miniature 292.252,96.262 r90 top
TP27 "5015" Testpoint_Keystone_Miniature 292.751,64.766 r90 top
TP28 "5015" Testpoint_Keystone_Miniature 290.09,156.98 r90 top
TP29 "5015" Testpoint_Keystone_Miniature 16.155,88.714 r90 top
TP31 "5015" Testpoint_Keystone_Miniature 2.858,23.044 r90 top
U1 "SN74LVC1G11DBVR" DBV0006A_N 12.578,38.017 r270 bottom
U2 "TMCS1133B1QDVGR" DVG0010A-MFG 223.76,21.08 r270 bottom
U3 "ISOW1044DFM" DFM0020A-MFG 12.99,151.39 r90 bottom
U4 "TPS26400PWPR" PWP0016H-MFG 8.607,119.487 r270 bottom
U5 "TPS7A2033PDBVR" DBV0005A-MFG 8.408,92.892 r0 bottom
U6 "TPS7A2033PDBVR" DBV0005A-MFG 8.526,88.6 r0 bottom
U7 "TLVM13620RDHR" RDH0030A-MFG 8.251,102.735 r180 bottom
U8 "TMUX1204DGSR" DGS0010A-MFG 15.025,47.681 r270 bottom
U9 "TLV76050DBZR" DBZ0003A_N 256.796,136.816 r180 bottom
U10 "AMC1306M05DWVR" DWV0008A 268.94,147.5 r0 bottom
U11 "OPA2320AIDRGT" DRG0008A 14.805,74.409 r0 bottom
U12 "AMC1336DWVR" DWV0008A 269.093,156.462 r0 bottom
U13 "AMC1336DWVR" DWV0008A 269.1,164.78 r0 bottom
U14 "UCC14141QDWNRQ1" DWJ0036A-MFG 33.841,84.106 r0 bottom
U15 "TMCS1133B1QDVGR" DVG0010A-MFG 80.467,21.184 r270 bottom
U16 "TLV76050DBZR" DBZ0003A_N 61.997,133.426 r180 bottom
U18 "AMC1302QDWVRQ1" DWV0008A 55.36,156.32 r180 bottom
U21 "AMC1311BDWVR" DWV0008A 55.403,146.917 r180 bottom
U24 "UCC14141QDWNRQ1" DWJ0036A-MFG 33.74,112.36 r0 bottom
U25 "OPA320AIDBVR" DBV0005A_N 6.85,84.498 r180 bottom
U26 "SN74LVC126APWR" PW0014A_N 14.443,60.171 r270 bottom
U27 "UCC14141QDWNRQ1" DWJ0036A-MFG 277.5,70.68 r180 bottom
U28 "UCC14141QDWNRQ1" DWJ0036A-MFG 277.5,42.195 r180 bottom
U29 "UCC21710QDWQ1" DW0016B_HV 33.991,96.145 r180 bottom
U30 "UCC21710QDWQ1" DW0016B_HV 33.89,124.386 r180 bottom
U31 "SN74LVC126APWR" PW0014A_N 19.914,7.727 r270 bottom
U32 "UCC14141QDWNRQ1" DWJ0036A-MFG 33.88,56.04 r0 bottom
U33 "UCC14141QDWNRQ1" DWJ0036A-MFG 33.88,27 r0 bottom
U34 "UCC21710QDWQ1" DW0016B_HV 277.35,58.8 r0 bottom
U35 "UCC21710QDWQ1" DW0016B_HV 277.35,30.153 r0 bottom
U36 "UCC14141QDWNRQ1" DWJ0036A-MFG 277.451,98.713 r180 bottom
U37 "UCC21710QDWQ1" DW0016B_HV 34.03,38.84 r180 bottom
U38 "UCC21710QDWQ1" DW0016B_HV 33.991,67.912 r180 bottom
U39 "UCC14141QDWNRQ1" DWJ0036A-MFG 277.5,126.605 r180 bottom
U40 "UCC21710QDWQ1" DW0016B_HV 277.35,114.736 r0 bottom
U41 "UCC21710QDWQ1" DW0016B_HV 277.33,86.676 r0 bottom
ZZ1 "This Assembly Note is for PCB labels only" AssemblyNoteLabel 6.35,197.95 r0 top
ZZ2 "These assemblies are ESD sensitive, ESD precautions shall be observed." AssemblyNote 6.35,195.41 r0 top
ZZ3 "These assemblies must be clean and free from flux and all contaminants. Use of no clean flux is not acceptable." AssemblyNote 6.35,192.87 r0 top
ZZ4 "These assemblies must comply with workmanship standards IPC-A-610 Class 2, unless otherwise specified." AssemblyNote 6.35,190.33 r0 top

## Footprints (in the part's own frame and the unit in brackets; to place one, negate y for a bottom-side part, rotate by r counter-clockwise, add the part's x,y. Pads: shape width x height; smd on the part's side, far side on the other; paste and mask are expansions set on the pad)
0402L [mm] "0402 from SM-752 data"
  rect 0.6x0.5 smd: 1(-0.5,0) 2(0.5,0)
  body extent -0.55,-0.3 0.55,0.3, height 0.6
0402S [mil] "Based on C0402S footprint from PADS legacy"
  rect 15x24 smd: 1(-20,0) 2(20,0)
  body extent -22,-12 22,12, height 24
0603 [mm] "0603 from SM-752 data"
  rect 1x0.95 smd: 1(-0.8,0) 2(0.8,0)
  silkscreen extent -1.52,-0.69 1.52,0.69, body extent -0.87,-0.47 0.87,0.47, height 1
0603S [mil]
  rect 20x35 smd: 1(-30,0) 2(30,0)
  body extent -34,-19 34,19, height 39
0805_HV [mil] "0805 with 30mil clearance between pads"
  rect 50x63 smd: 1(-40,0) 2(40,0)
  silkscreen extent -74,-40 74,40, body extent -43,-29 43,29, height 57
0805_HV1 [mm] "Custom footprint based on analyzing multiple manufacturer recommendations"
  rrect10% 1x1.25 smd: 1(-1,0) 2(1,0)
  silkscreen extent -0.2,-0.75 0.2,0.75, body extent -1.1,-0.72 1.1,0.73, height 1.45
1206 [mm] "1206 from SM-752 data"
  rect 1.3x1.85 smd: 1(-1.45,0) 2(1.45,0)
  silkscreen extent -2.4,-1.21 2.4,1.21, body extent -1.7,-0.9 1.7,0.9, height 1.35
1206_180L [mm] "1206_180"
  rect 1.1x1.75 smd: 1(-1.35,0) 2(1.35,0)
  silkscreen extent -0.4,-0.77 0.4,0.77, body extent -1.75,-0.95 1.75,0.95, height 1.8
1206_190L [mm] "1206_190"
  rect 1.1x1.75 smd: 1(-1.35,0) 2(1.35,0)
  silkscreen extent -0.4,-0.77 0.4,0.77, body extent -1.75,-0.95 1.75,0.95, height 1.9
1206L [mm] "1206 from SM-752 data"
  rect 1.1x1.75 smd: 1(-1.35,0) 2(1.35,0)
  silkscreen extent -0.4,-0.77 0.4,0.77, body extent -1.7,-0.9 1.7,0.9, height 1.35
1210 [mm] "1210 from SM-752 data"
  rect 1.3x2.7 smd: 1(-1.45,0) 2(1.45,0)
  silkscreen extent -2.32,-1.57 2.32,1.57, body extent -1.7,-1.35 1.7,1.35, height 1.35
1210_270 [mm] "1210"
  rect 1.3x2.7 smd: 1(-1.45,0) 2(1.45,0)
  silkscreen extent -2.32,-1.57 2.32,1.57, body extent -1.7,-1.35 1.7,1.35, height 2.7
1812_254 [mm] "SMD, 2-Leads, Body 4.8x3.4mm"
  rect 1.6x3.4 smd: 1(-2,0) 2(2,0)
  silkscreen extent -0.8,-1.7 0.8,1.7, body extent -2.4,-1.7 2.4,1.7, height 2.54
2220 [mm] "Chip Capacitor, Body 5.7x5.0mm, IPC Medium Density"
  rect 1.6x5.3 smd: 1(-2.6,0) 2(2.6,0)
  silkscreen extent -3.69,-2.94 3.69,2.94, body extent -2.95,-2.62 2.95,2.62, height 1.35
2220_280 [mm] "Chip Capacitor, Body 5.7x5.0mm, IPC Medium Density"
  rect 1.6x5.3 smd: 1(-2.6,0) 2(2.6,0)
  silkscreen extent -3.69,-2.94 3.69,2.94, body extent -2.95,-2.62 2.95,2.62, height 2.8
AssemblyNote [mm] "Assembly Note"
AssemblyNoteLabel [mm] "Assembly Note for PCB Labels"
CAPRD1000W60D900H1200 [mm] "Disk, Radial Capacitor"
  round 1.35 hole 0.85: 1(-5,0) 2(5,0)
  silkscreen extent -5.3,-3.5 5.3,3.5, body extent -4.48,-3.5 4.48,3.5, height 11.99
CE_Mark_5mm [mm] "Minimum text height for CE Mark"
  silkscreen extent -3.5,-2.5 3.5,2.5
controlCARD-120HSEC [mm] "Pads are not numbered according to Samtec datasheet."
  rect 0.5x2.724 smd: 1(-23.357,-1.678) 2(-23.357,1.722) 3(-22.557,-1.678) 4(-22.557,1.722) 5(-21.757,-1.678) 6(-21.757,1.722) 7(-20.957,-1.678) 8(-20.957,1.722) 9(-20.157,-1.678) 10(-20.157,1.722) 11(-19.357,-1.678) 12(-19.357,1.722) 13(-18.557,-1.678) 14(-18.557,1.722) 15(-17.757,-1.678) 16(-17.757,1.722) 17(-16.957,-1.678) 18(-16.957,1.722) 19(-16.157,-1.678) 20(-16.157,1.722) 21(-15.357,-1.678) 22(-15.357,1.722) 23(-14.557,-1.678) 24(-14.557,1.722) 25(-13.757,-1.678) 26(-13.757,1.722) 27(-12.957,-1.678) 28(-12.957,1.722) 29(-12.157,-1.678) 30(-12.157,1.722) 31(-11.357,-1.678) 32(-11.357,1.722) 33(-10.557,-1.678) 34(-10.557,1.722) 35(-9.757,-1.678) 36(-9.757,1.722) 37(-8.957,-1.678) 38(-8.957,1.722) 39(-8.157,-1.678) 40(-8.157,1.722) 41(-7.357,-1.678) 42(-7.357,1.722) 43(-6.557,-1.678) 44(-6.557,1.722) 45(-5.757,-1.678) 46(-5.757,1.722) 47(-4.957,-1.678) 48(-4.957,1.722) 49(-4.157,-1.678) 50(-4.157,1.722) 51(-3.357,-1.678) 52(-3.357,1.722) 53(-2.557,-1.678) 54(-2.557,1.722) 55(-1.757,-1.678) 56(-1.757,1.722) 57(2.243,-1.678) 58(2.243,1.722) 59(3.043,-1.678) 60(3.043,1.722) 61(3.843,-1.678) 62(3.843,1.722) 63(4.643,-1.678) 64(4.643,1.722) 65(5.443,-1.678) 66(5.443,1.722) 67(6.243,-1.678) 68(6.243,1.722) 69(7.043,-1.678) 70(7.043,1.722) 71(7.843,-1.678) 72(7.843,1.722) 73(8.643,-1.678) 74(8.643,1.722) 75(9.443,-1.678) 76(9.443,1.722) 77(10.243,-1.678) 78(10.243,1.722) 79(11.043,-1.678) 80(11.043,1.722) 81(11.843,-1.678) 82(11.843,1.722) 83(12.643,-1.678) 84(12.643,1.722) 85(13.443,-1.678) 86(13.443,1.722) 87(14.243,-1.678) 88(14.243,1.722) 89(15.043,-1.678) 90(15.043,1.722) 91(15.843,-1.678) 92(15.843,1.722) 93(16.643,-1.678) 94(16.643,1.722) 95(17.443,-1.678) 96(17.443,1.722) 97(18.243,-1.678) 98(18.243,1.722) 99(19.043,-1.678) 100(19.043,1.722) 101(19.843,-1.678) 102(19.843,1.722) 103(20.643,-1.678) 104(20.643,1.722) 105(21.443,-1.678) 106(21.443,1.722) 107(22.243,-1.678) 108(22.243,1.722) 109(23.043,-1.678) 110(23.043,1.722) 111(23.843,-1.678) 112(23.843,1.722) 113(24.643,-1.678) 114(24.643,1.722) 115(25.443,-1.678) 116(25.443,1.722) 117(26.243,-1.678) 118(26.243,1.722) 119(27.043,-1.678) 120(27.043,1.722)
  round 0.025 hole 1.27 unplated mask+0.876: 181(-24.857,0.022) 182(28.543,1.522)
  round 1.348 hole 0.84: 185(-27.207,0.022) 186(30.893,0.022)
  silkscreen extent -32.11,-3.86 35.8,3.9, body extent -31.75,-3.48 35.3,3.52, height 12.35
CUI_PJ-002AH-SMT [mm] "CUI"
  rect 2.8x2.4 smd: 1(-3.05,5.7) 1A(3.05,5.7) 2(-3.05,-5.7) 3(3.05,-5.7)
  round 1 hole 1.6 unplated: MH1(-3.05,0)
  round 1.524 hole 1.8 unplated: MH2(1.45,0)
  silkscreen extent -8.05,-4.5 6.75,5.45, body extent -8.05,-6.3 6.75,6.3, height 11.2
DBV0005A-MFG [mm]
  rrect17% 1.1x0.6 smd paste+0 mask+0: 1(-1.3,0.95) 2(-1.3,0) 3(-1.3,-0.95) 4(1.3,-0.95) 5(1.3,0.95)
  silkscreen extent -2.18,-1.53 0.87,2.09, body extent -1.4,-1.45 1.4,1.45, height 1.45
DBV0005A_N [mm] "SOT23, 5-Leads, Body 2.9x1.6mm, Pitch 0.95mm, Lead Span 2.8mm, IPC Medium Density"
  rrect17% 1x0.6 smd: 1(-1.375,0.95) 2(-1.375,0) 3(-1.375,-0.95) 4(1.375,-0.95) 5(1.375,0.95)
  silkscreen extent -0.25,-1.55 0.25,1.55, body extent -1.42,-1.46 1.42,1.46, height 1.09
DBV0006A_N [mm] "SOT23, 6-Leads, Body 2.9x1.6mm, Pitch 0.95mm, Lead Span 2.8mm, IPC Medium Density"
  rrect17% 1x0.6 smd: 1(-1.375,0.95) 2(-1.375,0) 3(-1.375,-0.95) 4(1.375,-0.95) 5(1.375,0) 6(1.375,0.95)
  silkscreen extent -1.68,-1.55 0.5,1.55, body extent -1.42,-1.46 1.42,1.46, height 1.12
DBZ0003A_N [mm] "SOT23, 3-Leads, Body 2.9x1.3mm, Pitch 0.95mm, Lead Span 2.4mm, IPC Medium Density"
  rrect17% 1x0.6 smd: 1(-1.2,0.95) 2(-1.2,-0.95) 3(1.2,0)
  silkscreen extent 0.2,-1.5 0.7,1.5, body extent -1.26,-1.46 1.26,1.46, height 0.98
DEC0002A [mm] "X1SON-2"
  rrect57% 0.35x0.6 smd paste-0.5 mask-0.05: 1(-0.325,0) 2(0.325,0)
  rrect33% 0.3x0.5 on Top Paste: 1S(-0.35,0) 2S(0.35,0)
  body extent -0.5,-0.3 0.5,0.3, height 0.5
DFM0020A-MFG [mm]
  rrect17% 2.1x0.6 smd paste+0 mask+0: 1(-4.85,5.715) 2(-4.85,4.445) 3(-4.85,3.175) 4(-4.85,1.905) 5(-4.85,0.635) 6(-4.85,-0.635) 7(-4.85,-1.905) 8(-4.85,-3.175) 9(-4.85,-4.445) 10(-4.85,-5.715) 11(4.85,-5.715) 12(4.85,-4.445) 13(4.85,-3.175) 14(4.85,-1.905) 15(4.85,-0.635) 16(4.85,0.635) 17(4.85,1.905) 18(4.85,3.175) 19(4.85,4.445) 20(4.85,5.715)
  silkscreen extent -6.35,-6.47 3.4,6.69, body extent -5.15,-6.42 5.15,6.42, height 3.55
DGS0010A-MFG [mm]
  rrect33% 1.45x0.3 smd paste+0 mask+0: 1(-2.2,1) 2(-2.2,0.5) 3(-2.2,0) 4(-2.2,-0.5) 5(-2.2,-1) 6(2.2,-1) 7(2.2,-0.5) 8(2.2,0) 9(2.2,0.5) 10(2.2,1)
  silkscreen extent -3.6,-1.55 1.05,1.55, body extent -2.45,-1.5 2.45,1.5, height 1.1
DRG0008A [mm] "SON, 8-Leads, Body 3x3mm, Pitch 0.5mm, Thermal Pad 2x1.2mm, TI Recommended"
  oval 0.7x0.25 smd: 1(-1.35,0.75) 2(-1.35,0.25) 3(-1.35,-0.25) 4(-1.35,-0.75) 5(1.35,-0.75) 6(1.35,-0.25) 7(1.35,0.25) 8(1.35,0.75)
  rect 1.2x2 smd paste-0.6: 9(0,0)
  Drill Guide keep-out region: 0.6,-1.3 -0.6,-1.3 -0.6,-1 0.6,-1
  Drill Guide keep-out region: -0.6,1.3 0.6,1.3 0.6,1 -0.6,1
  silkscreen extent -1.7,-1.7 1.7,1.7, body extent -1.55,-1.55 1.55,1.55, height 0.81
DVG0010A-MFG [mm]
  rrect6% 1.65x4.41 smd paste+0 mask+0: 1(-4.875,2.54) 2(-4.875,-2.54)
  rrect17% 1.65x0.6 smd paste+0 mask+0: 3(4.875,-4.445) 4(4.875,-3.175) 5(4.875,-1.905) 6(4.875,-0.635) 7(4.875,0.635) 8(4.875,1.905) 9(4.875,3.175) 10(4.875,4.445)
  silkscreen extent -6.37,-5.25 3.67,5.25, body extent -5.15,-5.15 5.15,5.15, height 2.65
DW0016B_HV [mm] "SOIC-16, HV/isolation option"
  rrect17% 1.65x0.6 smd: 1(-4.875,4.445) 2(-4.875,3.175) 3(-4.875,1.905) 4(-4.875,0.635) 5(-4.875,-0.635) 6(-4.875,-1.905) 7(-4.875,-3.175) 8(-4.875,-4.445) 9(4.875,-4.445) 10(4.875,-3.175) 11(4.875,-1.905) 12(4.875,-0.635) 13(4.875,0.635) 14(4.875,1.905) 15(4.875,3.175) 16(4.875,4.445)
  body extent -5.17,-5.15 5.17,5.15, height 2.59
DWJ0036A-MFG [mm]
  rrect22% 1.85x0.45 smd paste+0 mask+0: 1(-4.975,5.525) 2(-4.975,4.875) 3(-4.975,4.225) 4(-4.975,3.575) 5(-4.975,2.925) 6(-4.975,2.275) 7(-4.975,1.625) 8(-4.975,0.975) 9(-4.975,0.325) 10(-4.975,-0.325) 11(-4.975,-0.975) 12(-4.975,-1.625) 13(-4.975,-2.275) 14(-4.975,-2.925) 15(-4.975,-3.575) 16(-4.975,-4.225) 17(-4.975,-4.875) 18(-4.975,-5.525) 19(4.975,-5.525) 20(4.975,-4.875) 21(4.975,-4.225) 22(4.975,-3.575) 23(4.975,-2.925) 24(4.975,-2.275) 25(4.975,-1.625) 26(4.975,-0.975) 27(4.975,-0.325) 28(4.975,0.325) 29(4.975,0.975) 30(4.975,1.625) 31(4.975,2.275) 32(4.975,2.925) 33(4.975,3.575) 34(4.975,4.225) 35(4.975,4.875) 36(4.975,5.525)
  silkscreen extent -6.28,-6.47 3.8,6.47, body extent -5.15,-6.42 5.15,6.42, height 3.55
DWV0008A [mm] "SOIC, 8-Leads, Body 5.95x7.6mm (max), Pitch 1.27mm"
  rrect17% 1.8x0.6 smd: 1(-5.45,1.905) 2(-5.45,0.635) 3(-5.45,-0.635) 4(-5.45,-1.905) 5(5.45,-1.905) 6(5.45,-0.635) 7(5.45,0.635) 8(5.45,1.905)
  silkscreen extent -6.25,-2.95 2.98,2.95, body extent -5.77,-2.92 5.77,2.93, height 2.67
ESD_Overlay_Medium [mm]
  silkscreen extent -3.22,-2.77 3.17,2.8
FCC_disclaimer [mm]
Fiducial10-20 [mm]
  round 1 smd mask+0.5: 1(0,0)
  Top Layer keep-out circle w1.178: c0,0 r0.5
FP-1474C_HEX_STANDOFF_8-32_1IN2-MFG [mil]
  round 169.5 hole 169.5 unplated paste-99999 mask+0: ""(0,0)
  silkscreen extent -147,-147 147,147, body extent -145,-125 144,125, height 505
FP-61259_PTH_XFRMR_130MM0_90MM0-MFG [mm]
  rrect2% 5.15x5.15 hole 3.4 paste-2539.97 mask+0: 1(-58.02,17.78)
  round 5.15 hole 3.4 paste-2539.97 mask+0: 2(-58.02,-17.78) 4(58.02,17.78)
  round 5.15 hole 3.6 paste-2539.97 mask+0: 3(58.02,-17.78)
  round 5.7 hole 5.7 unplated paste-2539.97 mask+0: ""(-51,-38) ""(-51,38) ""(51,-38) ""(51,38)
  silkscreen extent -65.62,-45 65,45, body extent -65,-45 65,45, height 52
FP-ACT45B-101-2P-TL003_SMT_4MM5_3MM2-MFG [mm]
  rrect11% 1.35x0.9 smd paste+0 mask+0: 1(-2.275,1.25) 2(-2.275,-1.25) 3(2.275,-1.25) 4(2.275,1.25)
  silkscreen extent -3.62,-1.7 2.35,1.7, body extent -2.25,-1.6 2.25,1.6, height 3
FP-B32716H1156K000_RADIAL-MFG [mm]
  round 2.05 hole 1.35 paste-2539.97 mask+0: 1(-18.75,-10.15) 2(18.75,-10.15) 2(18.75,10.15)
  rrect5% 2.05x2.05 hole 1.35 paste-2539.97 mask+0: 1(-18.75,10.2)
  silkscreen extent -21,-15 21,15, body extent -21.1,-15.05 21.1,15.15, height 0.25
FP-B32716H8306K000_RADIAL-MFG [mm]
  round 2.05 hole 1.35 paste-2539.97 mask+0: 1(-18.75,-10.15) 2(18.75,-10.15) 2(18.75,10.15)
  rrect5% 2.05x2.05 hole 1.35 paste-2539.97 mask+0: 1(-18.75,10.15)
  silkscreen extent -21,-15 21,15, body extent -21.1,-15.1 21.1,15.1, height 0.25
FP-CD-02-05-247_THERM_PAD_24MM13_19MM05-MFG [mm]
  body extent -12.16,-9.62 12.16,9.62, height 0.25
FP-CH0603-10RJFTA_0603-MFG [mm]
  rrect21% 0.475x0.9 smd paste+0 mask+0: 1(-0.617,0) 2(0.617,0)
  silkscreen extent -0.01,-0.43 0.01,0.43, body extent -0.76,-0.38 0.76,0.38, height 0.63
FP-CL10B104KA8VPJC_0603-MFG [mm]
  rrect13% 0.79x1 smd paste+0 mask+0: 1(-0.755,0) 2(0.755,0)
  silkscreen extent -0.9,-0.87 0.9,0.87, body extent -0.8,-0.4 0.8,0.4, height 0.9
FP-CL10B105KA8VPJC_0603-MFG [mm]
  rrect13% 0.79x1 smd paste+0 mask+0: 1(-0.755,0) 2(0.755,0)
  silkscreen extent -0.9,-0.87 0.9,0.87, body extent -0.8,-0.4 0.8,0.4, height 0.9
FP-CL10B105KL9VPJC_0603-MFG [mm]
  rrect12% 0.82x1.1 smd paste+0 mask+0: 1(-0.79,0) 2(0.79,0)
  silkscreen extent -0.95,-0.92 0.95,0.92, body extent -0.8,-0.4 0.8,0.4, height 1
FP-CR201-50VE_PTH_HEATSINKS_34MM0_50MM0-MFG [mm]
  rrect2% 4.07x4.07 hole 2.67 paste-2539.97 mask+0: 1(-23,1.25)
  round 4.07 hole 2.67 paste-2539.97 mask+0: 2(23,1.25)
  silkscreen extent -25,-17 25,17, body extent -25.13,-17.1 25.13,17.1, height 0.25
FP-CR0603-10W-000T_0603-MFG [mm]
  rrect10% 1x1 smd paste+0 mask+0: 1(-0.8,0) 2(0.8,0)
  silkscreen extent -0.85,-0.9 0.85,0.9, body extent -0.8,-0.4 0.8,0.4, height 0.55
FP-CSD17318Q2_WSON6-MFG [mm]
  rrect33% 0.45x0.3 smd paste+0 mask+0: 1(-0.975,0.65) 2(-0.975,0) 3(-0.975,-0.65) 4(0.975,-0.65) 5(0.975,0) 6(0.975,0.65)
  rrect33% 0.75x0.3 smd paste-1000 mask+0: 7(0.095,-0.65)
  rrect11% 1x0.95 smd paste-1000 mask+0: 8(0,0.325)
  body extent -1.07,-1.05 1.07,1.05, height 0.81
"FP-G9KB-1A DC12_PTH_RELAY_50MM0_36MM7-MFG" [mm]
  rrect5% 2.1x3.8 hole 3.2 slot 1.5 at 0 deg paste-2539.97 mask+0: 1(-20,12.35)
  rrect100% 2.1x3.8 hole 3.2 slot 1.5 at 0 deg paste-2539.97 mask+0: 2(20,12.35)
  rrect100% 13x3.7 hole 3.1 slot 12.4 at 0 deg paste-2539.97 mask+0: 3(-12.95,-6.4) 4(12.95,-6.4)
  silkscreen extent -25.87,-18.5 25.25,18.5, body extent -25.35,-18.6 25.35,18.6, height 0.25
"FP-KG DELLS1.22-JGKH-24_0603-MFG" [mm]
  rrect20% 1.05x0.5 smd paste-1000 mask+0: 1(-0.47,0)
  rrect20% 0.7x0.5 smd paste-1000 mask+0: 2(0.645,0)
  silkscreen extent -1.67,-0.63 0.75,0.63, body extent -0.8,-0.4 0.8,0.4, height 0.7
"FP-PMSSS 832 0063 PH_SCREW_0IN322-MFG" [mil]
  round 0 hole 177 unplated paste-99999 mask-39370.1: ""(0,0)
  silkscreen extent -161,-161 161,161, body extent -165,-165 165,165, height 10
FP-SMBJ36CA_DO-214AA-0 [mm]
  rrect5% 2.16x2.26 smd paste+0 mask+0: 1(-2.45,0) 2(2.45,0)
  silkscreen extent -2.37,-1.97 2.37,1.97, body extent -2.68,-1.81 2.68,1.81, height 2.65
FP-US1Q-TP_SMA-MFG [mm]
  rrect6% 1.78x2.16 smd paste+0 mask+0: 1(-2.025,0) 2(2.025,0)
  silkscreen extent -3.67,-1.46 2.37,1.46, body extent -2.66,-1.27 2.53,1.33, height 2.44
FP-WSL36371L500FEA_3637-MFG [mm]
  rrect6% 4.27x1.68 smd paste+0 mask+0: 1(-3.075,4.115) 2(3.075,4.115)
  rrect2% 4.27x7.62 smd paste+0 mask+0: 3(-3.075,-1.145) 4(3.075,-1.145)
  silkscreen extent -6.2,-5.4 4.7,5.4, body extent -4.52,-4.7 4.52,4.7, height 0.89
IEC_Caution_Medium [mm]
  silkscreen extent -5.51,-4.64 5.51,4.91
IEC_HighVoltage_Medium [mm]
  silkscreen extent -5.51,-4.46 5.51,5.09
IEC_HotSurface_Small [mm]
  silkscreen extent -2.72,-2.36 2.72,2.35
Keystone5003 [mil] "For Keystone 500x miniature loop terminals"
  round 80 hole 40: 1(0,0)
  silkscreen extent -52,-52 52,52, body extent -49,-49 49,49, height 182
Keystone5010 [mil] "Keystone Multipurpose loops"
  round 87 hole 63: 1(0,0)
  silkscreen extent -70,-70 70,70, body extent -63,-63 63,62, height 319
Keystone5011 [mil] "Keystone Multipurpose loops"
  round 87 hole 63: 1(0,0)
  silkscreen extent -70,-70 70,70, body extent -63,-63 63,62, height 319
Keystone_1902C [mil] "Hex Standoff, 4-40 threaded, nylon"
  round 1 on Mech4: 0(0,0)
  body extent -145,-126 146,126, height 501
Label_650x200 [mil] "Thermal Transfer Label"
  round 1 on Mech13: 0(0,0)
  silkscreen extent -325,-100 325,100, body extent -325,-100 325,100, height 1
